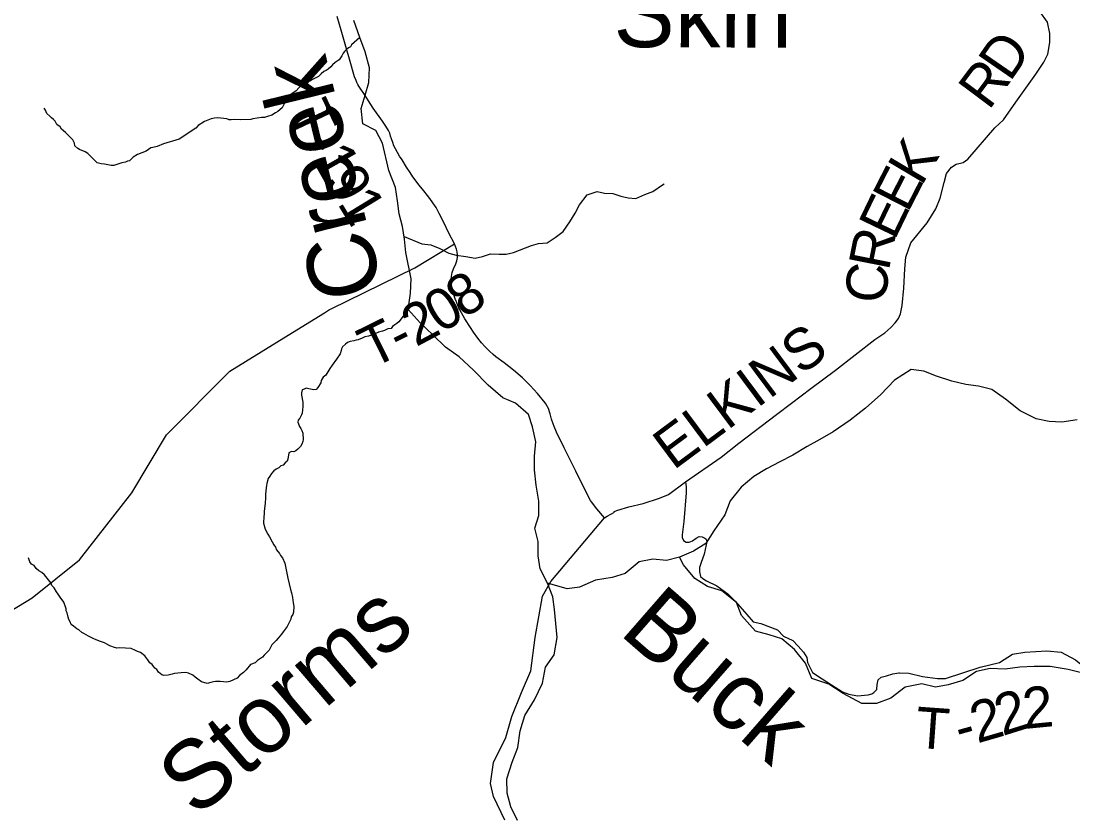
# Model space of a CAD drawing. Extents: x 0 to 34, y 0 to 22.
# Drawn here: x 6.132 to 7.584, y 18.121 to 19.223 of the extents above; entities that cross this region are included whole.
import ezdxf

# ---------------------------------------------------------------- set-up
doc = ezdxf.new("R2010")
doc.units = 0
for name, color, linetype in [('GM_X_County_Road', 7, 'Continuous'), ('GM_X_County_Road_Text', 7, 'Continuous'), ('GM_X_Minor_River', 7, 'Continuous'), ('GM_X_Minor_River_Text', 7, 'Continuous'), ('GM_X_Township_Road', 7, 'Continuous'), ('GM_X_Township_Road_Text', 7, 'Continuous')]:
    doc.layers.add(name, color=color, linetype=linetype)

msp = doc.modelspace()

# ---------------------------------------------------------------- linework, layer by layer
at = {"layer": 'GM_X_County_Road'}
msp.add_lwpolyline([(6.8001, 18.1189), (6.7846, 18.1516), (6.7804, 18.1699), (6.7846, 18.1988), (6.8014, 18.2333), (6.8098, 18.2622), (6.8231, 18.2953), (6.836, 18.3253), (6.8421, 18.3714), (6.8518, 18.4286), (6.8637, 18.4488), (6.9377, 18.5367), (6.9411, 18.539), (6.9461, 18.5417), (6.9514, 18.5442), (6.9508, 18.5454), (6.9559, 18.5472), (6.9712, 18.5519), (6.9908, 18.5563), (7.0136, 18.5638), (7.0259, 18.569), (7.0492, 18.5864), (7.0984, 18.6205), (7.1228, 18.6396), (7.175, 18.6794), (7.1957, 18.695), (7.2222, 18.715), (7.2563, 18.7407), (7.3104, 18.7827), (7.3242, 18.7919), (7.3326, 18.7994), (7.3389, 18.8057), (7.3432, 18.8118), (7.3461, 18.8181), (7.3484, 18.8299), (7.3507, 18.8535), (7.3521, 18.8803), (7.3536, 18.8964), (7.3603, 18.9163), (7.3827, 18.944), (7.3949, 18.9631), (7.401, 18.9781), (7.4065, 18.9998), (7.4095, 19.0121), (7.4163, 19.0209), (7.4228, 19.0247), (7.4323, 19.0271), (7.4391, 19.0318), (7.4762, 19.075), (7.4881, 19.0862), (7.5054, 19.1104), (7.533, 19.1492), (7.5438, 19.1658), (7.5493, 19.1767), (7.5523, 19.1927), (7.5522, 19.2055), (7.549, 19.2211), (7.5381, 19.2359)], dxfattribs=at)
at = {"layer": 'GM_X_Minor_River'}
for points in [[(6.6402, 19.0162), (6.6312, 19.0541), (6.6222, 19.0716), (6.604, 19.0808), (6.6018, 19.102), (6.6072, 19.1202), (6.6125, 19.1376), (6.6133, 19.1581), (6.6074, 19.1801), (6.5999, 19.1999), (6.5916, 19.2234)], [(6.5999, 19.1999), (6.5884, 19.1896), (6.5873, 19.187), (6.5842, 19.1855), (6.5815, 19.1833), (6.5788, 19.1807), (6.5769, 19.1781), (6.5749, 19.1743), (6.5714, 19.169), (6.566, 19.1653), (6.5622, 19.162), (6.5599, 19.1593), (6.5564, 19.156), (6.5534, 19.1541), (6.5503, 19.1527), (6.5465, 19.1497), (6.543, 19.146), (6.5346, 19.1419), (6.5311, 19.1397), (6.525, 19.1371), (6.522, 19.1368), (6.5189, 19.1342), (6.512, 19.1264), (6.5035, 19.1204), (6.5004, 19.1167), (6.4977, 19.1106), (6.4957, 19.108), (6.4926, 19.1028), (6.4868, 19.0975), (6.4838, 19.0957), (6.4784, 19.0924), (6.4727, 19.0906), (6.4685, 19.0895), (6.4643, 19.0892), (6.4522, 19.0875), (6.4495, 19.0868), (6.4359, 19.0862), (6.4264, 19.0864), (6.4226, 19.0861), (6.4196, 19.0861), (6.4162, 19.0873), (6.4041, 19.0887), (6.3996, 19.0884), (6.3946, 19.0873), (6.3858, 19.0837), (6.377, 19.0785), (6.3735, 19.0744), (6.3506, 19.0596), (6.3289, 19.0531), (6.3205, 19.0495), (6.3144, 19.048), (6.3117, 19.0473), (6.3052, 19.0429), (6.293, 19.0381), (6.2872, 19.0344), (6.2819, 19.0296), (6.2792, 19.0289), (6.2765, 19.0278), (6.2716, 19.0267), (6.2689, 19.026), (6.2662, 19.0249), (6.2605, 19.0231), (6.2567, 19.0232), (6.2477, 19.0249), (6.2428, 19.0253), (6.2375, 19.0269), (6.2308, 19.0335), (6.2245, 19.0397), (6.2211, 19.042), (6.2132, 19.0452), (6.2106, 19.0464), (6.2068, 19.0503), (6.2062, 19.0541), (6.204, 19.0583), (6.2017, 19.061), (6.1965, 19.066), (6.1939, 19.0687), (6.1883, 19.0734), (6.1865, 19.0764), (6.182, 19.0796), (6.1794, 19.0842), (6.1772, 19.0868), (6.1746, 19.0888), (6.172, 19.0911), (6.1679, 19.095), (6.1664, 19.0996), (6.1642, 19.1023)], [(6.8176, 18.1185), (6.8085, 18.1375), (6.8033, 18.1565), (6.8026, 18.1763), (6.8102, 18.199), (6.8179, 18.2195), (6.821, 18.2423), (6.8278, 18.2635), (6.8408, 18.2855), (6.8522, 18.3082), (6.856, 18.3302), (6.8682, 18.3476), (6.8721, 18.3712), (6.8706, 18.3909), (6.8684, 18.4099), (6.8662, 18.4273), (6.8587, 18.4463), (6.8489, 18.4661), (6.8459, 18.4843), (6.846, 18.5041), (6.8415, 18.5223), (6.8469, 18.5397), (6.8469, 18.5595), (6.8432, 18.5815), (6.841, 18.6028), (6.841, 18.6217), (6.8426, 18.6415), (6.8381, 18.662), (6.8329, 18.6794), (6.8148, 18.6947), (6.7974, 18.7023), (6.777, 18.7198), (6.7566, 18.7404), (6.737, 18.7587), (6.7181, 18.7724), (6.7008, 18.7891), (6.6834, 18.8059), (6.6668, 18.8241), (6.6699, 18.8469), (6.6707, 18.8666), (6.6633, 18.903), (6.6618, 18.9213), (6.6588, 18.9387), (6.6544, 18.9562), (6.6521, 18.9744), (6.6492, 18.9926), (6.6402, 19.0162)], [(6.6611, 18.9252), (6.6854, 18.9147), (6.6979, 18.9135), (6.7104, 18.9086), (6.7229, 18.9018), (6.7327, 18.8991), (6.746, 18.8972), (6.7589, 18.8949), (6.7691, 18.8972), (6.7801, 18.901), (6.7922, 18.9006), (6.802, 18.9006), (6.8122, 18.9029), (6.8368, 18.9127), (6.8467, 18.9154), (6.8584, 18.9165), (6.8694, 18.9237), (6.8807, 18.9321), (6.8898, 18.9453), (6.897, 18.9574), (6.9031, 18.9688), (6.9137, 18.9825), (6.9273, 18.987), (6.9375, 18.9851), (6.9489, 18.9843), (6.9602, 18.9809), (6.9704, 18.9783), (6.9807, 18.9775), (6.9932, 18.9828), (7.0041, 18.987), (7.0178, 18.9965), (7.0197, 18.9976)], [(6.6668, 18.8241), (6.6537, 18.8074), (6.651, 18.8048), (6.6483, 18.803), (6.6452, 18.8007), (6.6433, 18.7981), (6.6384, 18.7974), (6.6342, 18.7952), (6.6311, 18.7941), (6.6258, 18.7931), (6.6197, 18.7902), (6.6121, 18.7876), (6.6067, 18.7866), (6.6033, 18.7847), (6.5976, 18.7822), (6.5949, 18.7818), (6.5919, 18.7811), (6.5866, 18.7801), (6.5831, 18.7786), (6.58, 18.7764), (6.5762, 18.7727), (6.5746, 18.77), (6.5742, 18.7674), (6.573, 18.7632), (6.5679, 18.7557), (6.5617, 18.7475), (6.5586, 18.7426), (6.5532, 18.7335), (6.5493, 18.7309), (6.5466, 18.726), (6.5462, 18.723), (6.5419, 18.7166), (6.5396, 18.714), (6.5365, 18.7133), (6.5297, 18.7149), (6.5259, 18.7154), (6.5233, 18.7143), (6.5202, 18.7132), (6.5194, 18.7094), (6.5193, 18.706), (6.5214, 18.6965), (6.5213, 18.6904), (6.5209, 18.6858), (6.5204, 18.6813), (6.5196, 18.6786), (6.5173, 18.6741), (6.5149, 18.6715), (6.5145, 18.6685), (6.5167, 18.6627), (6.5185, 18.66), (6.52, 18.657), (6.5211, 18.6535), (6.5217, 18.6448), (6.5213, 18.6421), (6.52, 18.6383), (6.5181, 18.6353), (6.5142, 18.6312), (6.5116, 18.629), (6.5089, 18.6279), (6.5055, 18.6283), (6.502, 18.6265), (6.5004, 18.6174), (6.4999, 18.6147), (6.4969, 18.6125), (6.4942, 18.6095), (6.4911, 18.6084), (6.488, 18.6058), (6.4846, 18.604), (6.4815, 18.6014), (6.478, 18.5976), (6.4757, 18.5939), (6.4734, 18.5909), (6.4718, 18.584), (6.4713, 18.5814), (6.4709, 18.578), (6.47, 18.5693), (6.4699, 18.5647), (6.4694, 18.5563), (6.468, 18.5457), (6.468, 18.5415), (6.4675, 18.5385), (6.467, 18.5294), (6.4691, 18.521), (6.4732, 18.5141), (6.4754, 18.5102), (6.479, 18.5033), (6.4813, 18.4995), (6.4838, 18.496), (6.4849, 18.4926), (6.489, 18.4872), (6.4905, 18.4845), (6.4931, 18.4814), (6.4963, 18.4742), (6.4988, 18.4627), (6.5005, 18.4532), (6.5044, 18.4375), (6.5058, 18.4329), (6.5069, 18.4268), (6.5079, 18.4192), (6.5089, 18.4143)], [(6.661, 18.8107), (6.661, 18.8108)], [(7.5898, 18.6718), (7.5686, 18.6689), (7.5512, 18.6697), (7.5331, 18.6735), (7.5112, 18.6842), (7.4908, 18.7002), (7.4719, 18.7139), (7.4537, 18.7185), (7.4363, 18.7209), (7.4167, 18.7255), (7.3955, 18.7324), (7.3781, 18.7393), (7.3607, 18.7416), (7.3379, 18.7265), (7.319, 18.7068), (7.2977, 18.6879), (7.2765, 18.6713), (7.2529, 18.6554), (7.2347, 18.6448), (7.2173, 18.635), (7.1976, 18.6229), (7.1794, 18.6139), (7.1612, 18.6041), (7.1437, 18.5935), (7.1263, 18.5791), (7.1111, 18.5602), (7.1035, 18.5405), (7.0883, 18.5185), (7.0776, 18.5011), (7.0602, 18.4905), (7.0412, 18.4822), (7.023, 18.4777), (7.0041, 18.4793), (6.9852, 18.4756), (6.9662, 18.4597), (6.948, 18.4544), (6.9253, 18.4507), (6.9033, 18.4409), (6.8859, 18.4387), (6.8587, 18.4463)], [(6.5089, 18.4143), (6.5084, 18.4063), (6.5076, 18.4033), (6.5053, 18.3999), (6.5048, 18.3968), (6.5025, 18.3919), (6.4997, 18.3867), (6.4943, 18.3792), (6.492, 18.3758), (6.4873, 18.3702), (6.4846, 18.3672), (6.4784, 18.3612), (6.4749, 18.354), (6.4726, 18.3514), (6.468, 18.3469), (6.4657, 18.3443), (6.4587, 18.3395), (6.4553, 18.3365), (6.4492, 18.3339), (6.443, 18.3268), (6.4395, 18.3231), (6.4341, 18.319), (6.4307, 18.3152), (6.4207, 18.3105), (6.4158, 18.3098), (6.4116, 18.3102), (6.4071, 18.3107), (6.4007, 18.3108), (6.398, 18.3101), (6.3942, 18.309), (6.3893, 18.308), (6.3813, 18.31), (6.3765, 18.3139), (6.3727, 18.3166), (6.3694, 18.3193), (6.3637, 18.3221), (6.36, 18.3229), (6.3535, 18.3226), (6.3486, 18.322), (6.344, 18.3217), (6.341, 18.3209), (6.3357, 18.3195), (6.3296, 18.3189), (6.3266, 18.3197), (6.3221, 18.3235), (6.3199, 18.327), (6.3173, 18.329), (6.3132, 18.334), (6.3102, 18.3363), (6.3073, 18.3405), (6.3032, 18.3459), (6.2972, 18.3506), (6.2931, 18.3522), (6.2904, 18.3534), (6.2844, 18.3561), (6.2689, 18.3571), (6.2647, 18.3568), (6.2602, 18.3581), (6.2576, 18.3589), (6.255, 18.36), (6.2508, 18.362), (6.2474, 18.364), (6.2422, 18.366), (6.2361, 18.368), (6.232, 18.3699), (6.2256, 18.3731), (6.2193, 18.377), (6.2163, 18.3782), (6.2121, 18.3817), (6.2095, 18.3833), (6.2047, 18.3871), (6.2017, 18.3895), (6.2002, 18.3929), (6.1984, 18.3964), (6.1973, 18.3994), (6.1959, 18.4055), (6.1948, 18.4082), (6.1945, 18.4109), (6.1938, 18.4139), (6.1916, 18.4201), (6.1864, 18.427), (6.1839, 18.4312), (6.1813, 18.4343), (6.1783, 18.4397), (6.175, 18.4431), (6.1739, 18.4462), (6.1665, 18.4555), (6.1646, 18.4581), (6.1613, 18.4609), (6.1568, 18.4636), (6.1534, 18.4667), (6.1505, 18.4706), (6.1471, 18.4725), (6.1445, 18.476), (6.1427, 18.4813)], [(7.5956, 18.3227), (7.5774, 18.3273), (7.5525, 18.3312), (7.5305, 18.3312), (7.5108, 18.3305), (7.4904, 18.3276), (7.4699, 18.3284), (7.451, 18.3246), (7.432, 18.3118), (7.4116, 18.3058), (7.3942, 18.3028), (7.3753, 18.3074), (7.3525, 18.3029), (7.3328, 18.2878), (7.3131, 18.2803), (7.2927, 18.2803), (7.267, 18.2941), (7.2473, 18.307), (7.2239, 18.3147), (7.2149, 18.336), (7.1998, 18.355), (7.1824, 18.3695), (7.165, 18.3748), (7.1461, 18.3802), (7.1265, 18.4015), (7.1197, 18.4198), (7.0994, 18.4358), (7.0797, 18.4419), (7.0623, 18.4526), (7.0465, 18.4716), (7.0412, 18.4822)]]:
    msp.add_lwpolyline(points, dxfattribs=at)
at = {"layer": 'GM_X_Township_Road'}
for points in [[(6.7878, 18.7589), (6.7839, 18.762), (6.7787, 18.7668), (6.7727, 18.7726), (6.7679, 18.7782), (6.7627, 18.7847), (6.7569, 18.7929), (6.7527, 18.7996), (6.7448, 18.8113), (6.7381, 18.8236), (6.7368, 18.826), (6.7324, 18.837), (6.7321, 18.8378), (6.7275, 18.8518), (6.7268, 18.856), (6.7262, 18.8615), (6.7261, 18.8657), (6.7265, 18.8698), (6.7272, 18.8751), (6.7294, 18.8804), (6.7324, 18.8872), (6.734, 18.8916), (6.7348, 18.896), (6.7349, 18.8998), (6.7344, 18.904), (6.7333, 18.9075), (6.7307, 18.9147), (6.723, 18.9297), (6.7153, 18.9453), (6.7093, 18.9568), (6.7055, 18.9649), (6.6953, 18.9795), (6.6865, 18.9906), (6.6815, 18.9965), (6.6775, 19.0014), (6.673, 19.0075), (6.6693, 19.0133), (6.6644, 19.0209), (6.6582, 19.0309), (6.6549, 19.0358), (6.6519, 19.041), (6.6491, 19.0462), (6.6471, 19.0504), (6.6456, 19.055), (6.6437, 19.0601), (6.6425, 19.0638), (6.6413, 19.0677), (6.6396, 19.0716), (6.6358, 19.0774), (6.6312, 19.0845), (6.6184, 19.1024), (6.6062, 19.1213), (6.5997, 19.1312), (6.5987, 19.1328), (6.5971, 19.135), (6.5957, 19.1376), (6.5947, 19.1403), (6.5928, 19.1457), (6.5856, 19.17), (6.5814, 19.184), (6.5749, 19.2067), (6.5686, 19.2289)], [(6.5605, 18.8253), (6.676, 18.8818), (6.7307, 18.9147)], [(5.9566, 18.2896), (6.0001, 18.3383), (6.015, 18.3469), (6.0652, 18.3759), (6.1478, 18.426), (6.2129, 18.4786), (6.2855, 18.5713), (6.333, 18.6514), (6.4207, 18.7391), (6.5069, 18.7924), (6.5513, 18.8198), (6.5583, 18.8242), (6.5605, 18.8253)], [(6.9377, 18.5367), (6.9271, 18.5488), (6.9195, 18.5586), (6.9182, 18.5607), (6.9084, 18.5795), (6.8979, 18.6009), (6.8821, 18.6332), (6.8713, 18.655), (6.8679, 18.6629), (6.8666, 18.6664), (6.8645, 18.6728), (6.8625, 18.68), (6.8619, 18.6829), (6.8609, 18.686), (6.8606, 18.6868), (6.8566, 18.6939), (6.8555, 18.6952), (6.8449, 18.7082), (6.8352, 18.7195), (6.8285, 18.7258), (6.8242, 18.7298), (6.8118, 18.7406), (6.7991, 18.7505), (6.7878, 18.7589)], [(7.0492, 18.5864), (7.0501, 18.5793), (7.0505, 18.5711), (7.0471, 18.5314), (7.0448, 18.5129), (7.0448, 18.5092), (7.0466, 18.5055), (7.0505, 18.5028), (7.0542, 18.5031), (7.0591, 18.505), (7.0641, 18.5087), (7.068, 18.511), (7.0722, 18.5105), (7.0762, 18.5087), (7.0773, 18.5076)], [(7.0773, 18.5076), (7.0779, 18.5071), (7.079, 18.5041), (7.078, 18.4993), (7.0751, 18.4865), (7.0711, 18.4748), (7.0685, 18.4679), (7.0689, 18.4618), (7.0699, 18.4555), (7.0735, 18.453), (7.0784, 18.4494), (7.0928, 18.4427), (7.1077, 18.4316), (7.1178, 18.4213), (7.1341, 18.403), (7.1428, 18.3929), (7.1531, 18.3909), (7.1761, 18.3818), (7.1845, 18.3734), (7.1973, 18.3673), (7.2047, 18.3593), (7.212, 18.3512), (7.2167, 18.3438), (7.2177, 18.337), (7.2248, 18.3231), (7.2379, 18.3142), (7.2509, 18.306), (7.2658, 18.2961), (7.2746, 18.2932), (7.2868, 18.2906), (7.3013, 18.2921), (7.3066, 18.2936), (7.3091, 18.2953), (7.3133, 18.2997), (7.314, 18.3064), (7.315, 18.3127), (7.3194, 18.3168), (7.3266, 18.3186), (7.3353, 18.321), (7.3437, 18.3224), (7.3446, 18.3224)], [(7.3446, 18.3224), (7.3577, 18.3221), (7.3765, 18.3175), (7.3969, 18.3146), (7.4082, 18.3146), (7.4559, 18.3303), (7.4825, 18.3368), (7.5007, 18.3482), (7.5174, 18.3512), (7.5478, 18.3531), (7.5679, 18.3512), (7.5877, 18.3405), (7.6089, 18.3234), (7.6401, 18.2983), (7.6598, 18.2896), (7.678, 18.2842), (7.6928, 18.2789), (7.7076, 18.2747), (7.7243, 18.2683), (7.735, 18.2599), (7.7445, 18.2439), (7.7505, 18.2314), (7.7653, 18.2219)]]:
    msp.add_lwpolyline(points, dxfattribs=at)

# ---------------------------------------------------------------- texts
at = {"layer": 'GM_X_County_Road_Text'}
for s, height, rotation, p in [('D', 0.0568, 55.441, (7.4971, 19.1374)), ('R', 0.0568, 53.2136, (7.4678, 19.0981)), ('K', 0.0568, 59.28, (7.3749, 18.9935)), ('E', 0.0568, 62.8389, (7.3559, 18.9565)), ('E', 0.0568, 64.2888, (7.3377, 18.9186)), ('R', 0.0568, 78.714, (7.3297, 18.8764)), ('C', 0.0568, 84.7784, (7.3257, 18.8315)), ('ELKINS', 0.05682, 36.6473, (7.0327, 18.6015))]:
    msp.add_text(s, height=height, rotation=rotation, dxfattribs=at).set_placement(p)
at = {"layer": 'GM_X_Minor_River_Text'}
for s, height, rotation, p in [('Skin', 0.09469, 359.754, (6.9499, 19.1867)), ('Creek', 0.09472, 103.7568, (6.6325, 18.8505)), ('Buck', 0.09473, 318.9031, (6.9561, 18.3772)), ('Storms', 0.09472, 40.5166, (6.3743, 18.1208))]:
    msp.add_text(s, height=height, rotation=rotation, dxfattribs=at).set_placement(p)
at = {"layer": 'GM_X_Township_Road_Text'}
for s, rotation, p in [('T', 295.3973, (6.5007, 19.0964)), ('-', 299.3802, (6.5209, 19.0542)), ('1', 299.4462, (6.5324, 19.0338)), ('9', 299.8398, (6.5498, 19.0029)), ('1', 301.4077, (6.5681, 18.9711)), ('8', 34.93, (6.7445, 18.8107)), ('0', 31.4425, (6.7115, 18.7904)), ('2', 27.955, (6.6773, 18.7721)), ('T', 26.2112, (6.6166, 18.7422)), ('-', 26.2112, (6.6547, 18.7609)), ('2', 5.5454, (7.5171, 18.245)), ('2', 17.418, (7.4867, 18.2351)), ('T', 355.8663, (7.3653, 18.2193)), ('2', 16.2432, (7.4519, 18.2249)), ('-', 15.8124, (7.429, 18.2185))]:
    msp.add_text(s, height=0.0568, rotation=rotation, dxfattribs=at).set_placement(p)

doc.saveas('drawing.dxf')
